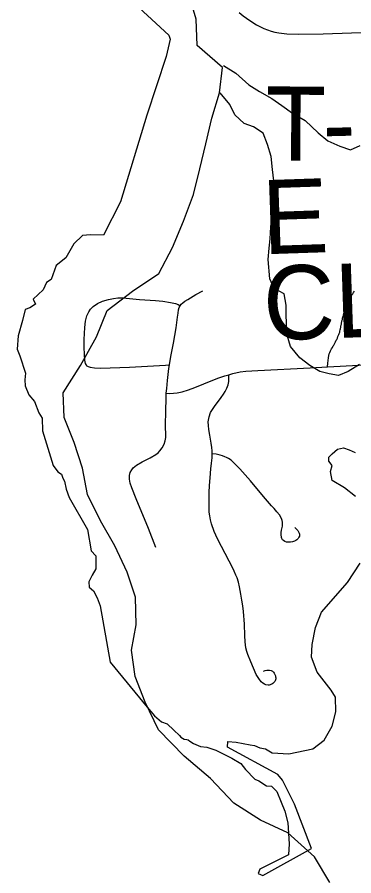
# Model space of a CAD drawing. Extents: x 63.4 to 97.4, y 0.4 to 22.4.
# Drawn here: x 67.709 to 67.967, y 19.757 to 20.415 of the extents above; entities that cross this region are included whole.
import ezdxf

# ---------------------------------------------------------------- set-up
doc = ezdxf.new("R2010")
doc.units = 0
for name, color, linetype in [('GM_X_County_Road', 7, 'Continuous'), ('GM_X_Major_Lake', 7, 'Continuous'), ('GM_X_Minor_River', 7, 'Continuous'), ('GM_X_Township_Road', 7, 'Continuous'), ('GM_X_Township_Road_Text', 7, 'Continuous'), ('SH_Cut_Line', 7, 'Continuous')]:
    doc.layers.add(name, color=color, linetype=linetype)

msp = doc.modelspace()

# ---------------------------------------------------------------- linework, layer by layer
at = {"layer": 'GM_X_County_Road'}
for points in [[(67.77988, 20.44361), (67.82559, 20.40119), (67.82657, 20.39823), (67.82361, 20.38475), (67.80865, 20.33987), (67.7886, 20.27328), (67.77544, 20.2478), (67.76557, 20.24813), (67.7595, 20.24747), (67.75275, 20.24106), (67.7465, 20.23038), (67.73927, 20.22445), (67.7354, 20.2138), (67.73188, 20.21164), (67.72924, 20.20588), (67.72152, 20.19881), (67.72333, 20.19503), (67.71905, 20.19207), (67.71544, 20.19075), (67.7133, 20.18237), (67.71001, 20.17053), (67.70935, 20.16034), (67.71132, 20.15541), (67.71576, 20.14209), (67.71527, 20.13699), (67.71544, 20.13222), (67.71823, 20.12548), (67.72267, 20.12039), (67.72596, 20.11168), (67.72842, 20.1074), (67.72875, 20.0977), (67.7368, 20.07123), (67.74042, 20.0663), (67.74338, 20.06449), (67.7442, 20.06137), (67.74552, 20.05923), (67.74683, 20.05298), (67.74905, 20.04672), (67.76329, 20.02222), (67.76607, 20.0058), (67.76969, 20.00185), (67.76969, 19.99183), (67.76689, 19.98705), (67.76426, 19.98196), (67.76447, 19.97796), (67.76771, 19.97505), (67.77051, 19.96979), (67.77297, 19.96355), (67.78054, 19.92042), (67.80896, 19.88581), (67.81449, 19.87929), (67.81991, 19.87468), (67.82435, 19.87304), (67.82945, 19.86827), (67.83372, 19.86417), (67.83471, 19.86285), (67.83734, 19.86121), (67.83931, 19.86104), (67.84046, 19.86088), (67.84161, 19.85989), (67.84441, 19.85791), (67.84967, 19.85562), (67.8546, 19.85529), (67.86151, 19.85282), (67.87367, 19.84674), (67.88058, 19.84263), (67.88419, 19.83819), (67.89139, 19.83054), (67.89455, 19.82947), (67.90047, 19.82553), (67.90425, 19.8252), (67.90573, 19.82372), (67.90836, 19.82109), (67.91165, 19.81303), (67.91428, 19.80613), (67.91667, 19.79719), (67.91773, 19.78096), (67.9172, 19.77271), (67.89512, 19.76154), (67.89406, 19.75835), (67.89752, 19.75675), (67.93476, 19.7775), (67.92186, 19.81142), (67.91268, 19.82977), (67.90895, 19.8343), (67.87052, 19.85531), (67.87078, 19.85943), (67.87704, 19.85903), (67.88781, 19.8569), (67.89113, 19.8565), (67.89526, 19.85464), (67.89952, 19.85397), (67.90457, 19.85092), (67.91758, 19.85009), (67.93582, 19.85384), (67.94447, 19.86049), (67.95072, 19.87127), (67.95338, 19.88217), (67.95325, 19.89348), (67.94992, 19.8988), (67.93915, 19.91263), (67.93476, 19.9242), (67.93543, 19.93391), (67.93795, 19.94708), (67.94261, 19.95865), (67.96242, 19.98153), (67.97214, 19.99642)], [(67.96841, 20.0475), (67.96016, 20.05402), (67.95059, 20.05974), (67.94939, 20.06665), (67.95072, 20.07131), (67.94806, 20.0745), (67.94806, 20.07769), (67.95059, 20.08009), (67.95471, 20.08368), (67.95923, 20.08474), (67.96375, 20.08328), (67.9684, 20.08119)]]:
    msp.add_lwpolyline(points, dxfattribs=at)
at = {"layer": 'GM_X_Major_Lake'}
msp.add_lwpolyline([(67.94886, 19.75138), (67.93709, 19.77115), (67.91659, 19.78939), (67.89572, 19.79927), (67.87522, 19.81219), (67.85738, 19.8312), (67.83726, 19.8483), (67.81752, 19.86845), (67.80727, 19.88973), (67.79967, 19.9095), (67.79701, 19.92965), (67.80042, 19.94904), (67.80003, 19.97033), (67.79357, 19.98933), (67.78408, 20.00948), (67.77307, 20.02886), (67.7632, 20.04901), (67.7594, 20.06915), (67.75294, 20.08892), (67.74534, 20.10793), (67.74458, 20.12693), (67.75785, 20.14784), (67.76999, 20.16989), (67.77834, 20.19003), (67.79769, 20.20486), (67.8178, 20.21855), (67.82842, 20.23831), (67.83676, 20.25846), (67.84435, 20.27898), (67.84928, 20.29875), (67.85383, 20.31775), (67.85838, 20.33751), (67.86444, 20.3569), (67.86672, 20.37628), (67.84736, 20.39338), (67.84659, 20.41353), (67.84052, 20.43329)], dxfattribs=at)
at = {"layer": 'GM_X_Minor_River'}
for points in [[(67.86743, 20.37798), (67.87695, 20.37194), (67.88687, 20.36323), (67.89487, 20.35795), (67.90439, 20.35267), (67.91201, 20.34738), (67.92039, 20.34133), (67.92991, 20.33567), (67.93984, 20.32621), (67.94746, 20.32016), (67.95659, 20.31602), (67.96458, 20.31339), (67.97216, 20.31647)], [(67.97152, 20.14874), (67.96281, 20.14338), (67.95562, 20.1403), (67.9484, 20.14141), (67.94117, 20.14328), (67.93356, 20.14781), (67.92593, 20.15386), (67.91867, 20.16257), (67.91558, 20.17283), (67.91547, 20.19412), (67.9139, 20.20287), (67.90629, 20.20701), (67.90283, 20.21423), (67.90162, 20.22905), (67.90233, 20.2378), (67.90305, 20.24503), (67.90376, 20.25416), (67.90448, 20.26177), (67.90482, 20.27014), (67.90516, 20.27813), (67.90586, 20.28954), (67.90505, 20.29829), (67.90386, 20.30817), (67.90116, 20.31728), (67.89769, 20.32601), (67.89045, 20.33093), (67.88322, 20.33355), (67.87598, 20.33998), (67.87214, 20.34795), (67.86488, 20.35705)]]:
    msp.add_lwpolyline(points, dxfattribs=at)
at = {"layer": 'GM_X_Township_Road'}
for points in [[(67.87941, 20.41862), (67.88255, 20.41605), (67.88748, 20.41235), (67.89268, 20.40912), (67.89819, 20.4064), (67.90391, 20.40423), (67.90684, 20.40344), (67.90983, 20.40289), (67.91595, 20.40228), (67.92522, 20.40203), (67.94386, 20.4023), (68.00163, 20.4043)], [(67.83424, 20.19374), (67.83508, 20.19494), (67.83615, 20.19597), (67.83779, 20.1971), (67.84, 20.19848), (67.84621, 20.20227), (67.85151, 20.20521)], [(67.94711, 20.14681), (67.94728, 20.14962), (67.94747, 20.15182), (67.94776, 20.15378), (67.94806, 20.1556), (67.94843, 20.15678), (67.94886, 20.15795), (67.94938, 20.15906), (67.94966, 20.15961), (67.94996, 20.16016), (67.95027, 20.16071), (67.95087, 20.16179), (67.95151, 20.16286), (67.95184, 20.16339), (67.95218, 20.16392), (67.95247, 20.16447), (67.95301, 20.16558), (67.9533, 20.16613), (67.95383, 20.16724), (67.95416, 20.16778), (67.95462, 20.16892), (67.95504, 20.17009), (67.95555, 20.17122), (67.95585, 20.17178), (67.95614, 20.17233), (67.95642, 20.17353), (67.95657, 20.17414), (67.95685, 20.17535), (67.95699, 20.17596), (67.95727, 20.17716), (67.9574, 20.17777), (67.95763, 20.17899), (67.95773, 20.17961), (67.95783, 20.18022), (67.95793, 20.18084), (67.95803, 20.18146), (67.95818, 20.18206), (67.95847, 20.18327), (67.95862, 20.18388), (67.95891, 20.18509), (67.95922, 20.18629), (67.9594, 20.18688), (67.95959, 20.18748), (67.95998, 20.18866), (67.96018, 20.18925), (67.96059, 20.19042), (67.961, 20.1916), (67.9612, 20.19219), (67.96142, 20.19277), (67.96164, 20.19336), (67.96187, 20.19394), (67.96235, 20.19508), (67.96261, 20.19565), (67.96312, 20.19679), (67.96338, 20.19735), (67.96364, 20.19792), (67.96392, 20.19848), (67.96448, 20.19958), (67.96508, 20.20067), (67.9654, 20.20121), (67.96573, 20.20174), (67.96607, 20.20227), (67.96641, 20.20279), (67.96711, 20.20381), (67.96784, 20.20481)], [(67.76284, 20.14746), (67.76179, 20.14943), (67.76126, 20.15205), (67.76087, 20.15624), (67.76061, 20.16188), (67.76074, 20.16791), (67.76113, 20.17709), (67.76179, 20.18194), (67.76281, 20.18593), (67.76427, 20.18915), (67.76558, 20.19112), (67.76755, 20.19309), (67.77098, 20.19531), (67.77476, 20.19715), (67.77922, 20.1986), (67.78302, 20.19936), (67.78643, 20.19978), (67.79023, 20.19978), (67.80295, 20.1986), (67.81524, 20.1976), (67.82088, 20.1972), (67.8268, 20.19631), (67.83059, 20.19543), (67.8326, 20.19462), (67.83424, 20.19374)], [(67.82599, 20.14829), (67.82708, 20.15468), (67.82904, 20.16504), (67.83114, 20.17684), (67.83219, 20.18502), (67.83271, 20.18811), (67.83305, 20.19055), (67.83354, 20.19232), (67.83424, 20.19374)], [(67.94711, 20.14681), (67.97106, 20.14802), (68.0557, 20.15015)], [(67.76284, 20.14746), (67.7652, 20.14654), (67.76847, 20.14602), (67.77306, 20.14589), (67.79548, 20.14668), (67.8231, 20.14814), (67.82599, 20.14829)], [(67.82356, 20.1267), (67.8239, 20.13026), (67.82441, 20.13632), (67.82552, 20.14554), (67.82599, 20.14829)], [(67.87144, 20.14076), (67.87467, 20.14171), (67.88021, 20.14294), (67.88443, 20.14349), (67.8937, 20.14408)], [(67.8937, 20.14408), (67.93391, 20.14615), (67.94711, 20.14681)], [(67.82356, 20.1267), (67.82628, 20.12641), (67.82899, 20.12655), (67.83199, 20.12684), (67.83585, 20.1277), (67.84057, 20.12913), (67.8454, 20.13094), (67.85933, 20.13673), (67.86392, 20.13843), (67.86838, 20.13987), (67.87144, 20.14076)], [(67.85877, 20.08017), (67.85868, 20.08232), (67.8584, 20.08505), (67.85792, 20.08842), (67.85687, 20.09457), (67.8562, 20.09868), (67.85586, 20.10179), (67.85575, 20.10458), (67.85631, 20.10847), (67.85753, 20.1118), (67.86042, 20.11641), (67.86565, 20.12337), (67.86743, 20.12581), (67.86876, 20.12782), (67.87009, 20.13038), (67.87087, 20.13304), (67.87143, 20.1356), (67.87158, 20.13794), (67.87144, 20.14076)], [(67.81564, 20.00843), (67.81005, 20.02278), (67.80061, 20.04573), (67.79707, 20.05399), (67.79602, 20.05766), (67.79536, 20.06081), (67.79532, 20.0622), (67.79536, 20.06356), (67.79602, 20.06579), (67.79707, 20.06775), (67.79828, 20.06936), (67.79942, 20.07055), (67.80065, 20.0715), (67.80506, 20.07405), (67.81135, 20.0772), (67.81546, 20.07968), (67.81726, 20.08103), (67.81868, 20.08249), (67.82048, 20.08483), (67.8219, 20.08747), (67.82282, 20.09002), (67.8232, 20.0927), (67.82315, 20.09621), (67.82302, 20.09962), (67.82302, 20.10316), (67.82315, 20.11181), (67.8234, 20.12391), (67.82356, 20.1267)], [(67.89797, 19.91349), (67.89929, 19.9139), (67.90048, 19.91421), (67.90166, 19.91421), (67.90264, 19.91416), (67.90391, 19.91398), (67.90489, 19.91344), (67.90573, 19.9126), (67.9063, 19.91184), (67.90684, 19.91081), (67.90718, 19.90983), (67.90737, 19.90906), (67.90747, 19.90844), (67.90747, 19.90756), (67.9073, 19.90681), (67.90706, 19.90615), (67.90671, 19.90559), (67.90633, 19.90507), (67.90571, 19.90443), (67.90515, 19.90393), (67.90449, 19.90348), (67.90378, 19.90317), (67.90304, 19.90298), (67.90231, 19.90283), (67.90161, 19.90275), (67.8999, 19.90298), (67.89875, 19.90344), (67.89745, 19.90423), (67.89629, 19.90521), (67.89449, 19.90774), (67.89247, 19.91099), (67.88824, 19.92066), (67.88612, 19.92622), (67.88531, 19.92866), (67.88457, 19.93146), (67.88402, 19.93593), (67.88369, 19.9408), (67.88357, 19.94947), (67.88268, 19.95925), (67.88223, 19.96359), (67.88157, 19.96781), (67.88079, 19.9726), (67.87967, 19.97815), (67.87878, 19.98171), (67.87778, 19.98494), (67.87691, 19.98704), (67.87556, 19.99016), (67.87345, 19.99439), (67.87167, 19.99784), (67.86285, 20.01495), (67.86018, 20.02058), (67.85812, 20.02649), (67.85736, 20.02951), (67.85682, 20.03252), (67.85654, 20.03541), (67.85631, 20.04153), (67.85654, 20.05042), (67.85676, 20.05576), (67.85709, 20.06166), (67.85776, 20.06855), (67.8582, 20.073), (67.85865, 20.077), (67.85877, 20.08017)], [(67.92199, 20.02353), (67.92331, 20.02249), (67.92439, 20.02131), (67.92498, 20.0204), (67.92544, 20.01942), (67.92565, 20.01852), (67.92568, 20.01771), (67.92555, 20.01708), (67.92524, 20.01635), (67.9246, 20.01532), (67.92356, 20.01423), (67.92276, 20.01364), (67.92189, 20.01316), (67.92032, 20.01257), (67.91872, 20.01236), (67.91722, 20.01236), (67.91562, 20.0125), (67.91433, 20.01299), (67.91336, 20.01358), (67.91266, 20.0143), (67.91214, 20.0151), (67.91179, 20.01597), (67.91148, 20.01824), (67.91158, 20.01984), (67.91196, 20.02162), (67.91259, 20.02472), (67.91273, 20.02611), (67.91271, 20.02766), (67.91238, 20.02914), (67.91188, 20.0306), (67.91035, 20.03324), (67.90839, 20.03562), (67.9062, 20.0381), (67.90424, 20.04039), (67.89818, 20.04742), (67.88815, 20.05941), (67.88003, 20.06863), (67.87566, 20.07299), (67.87316, 20.07517), (67.8712, 20.07648), (67.86967, 20.07735), (67.86843, 20.07789), (67.86674, 20.07867), (67.86476, 20.07922), (67.86187, 20.07978), (67.85877, 20.08017)]]:
    msp.add_lwpolyline(points, dxfattribs=at)
at = {"layer": 'SH_Cut_Line'}
for points in [[(67.77988, 20.44361), (67.82559, 20.40119), (67.82657, 20.39823), (67.82361, 20.38475), (67.80865, 20.33987), (67.7886, 20.27328), (67.77544, 20.2478), (67.76557, 20.24813), (67.7595, 20.24747), (67.75275, 20.24106), (67.7465, 20.23038), (67.73927, 20.22445), (67.7354, 20.2138), (67.73188, 20.21164), (67.72924, 20.20588), (67.72152, 20.19881), (67.72333, 20.19503), (67.71905, 20.19207), (67.71544, 20.19075), (67.7133, 20.18237), (67.71001, 20.17053), (67.70935, 20.16034), (67.71132, 20.15541), (67.71576, 20.14209), (67.71527, 20.13699), (67.71544, 20.13222), (67.71823, 20.12548), (67.72267, 20.12039), (67.72596, 20.11168), (67.72842, 20.1074), (67.72875, 20.0977), (67.7368, 20.07123), (67.74042, 20.0663), (67.74338, 20.06449), (67.7442, 20.06137), (67.74552, 20.05923), (67.74683, 20.05298), (67.74905, 20.04672), (67.76329, 20.02222), (67.76607, 20.0058), (67.76969, 20.00185), (67.76969, 19.99183), (67.76689, 19.98705), (67.76426, 19.98196), (67.76447, 19.97796), (67.76771, 19.97505), (67.77051, 19.96979), (67.77297, 19.96355), (67.78054, 19.92042), (67.80896, 19.88581), (67.81449, 19.87929), (67.81991, 19.87468), (67.82435, 19.87304), (67.82945, 19.86827), (67.83372, 19.86417), (67.83471, 19.86285), (67.83734, 19.86121), (67.83931, 19.86104), (67.84046, 19.86088), (67.84161, 19.85989), (67.84441, 19.85791), (67.84967, 19.85562), (67.8546, 19.85529), (67.86151, 19.85282), (67.87367, 19.84674), (67.88058, 19.84263), (67.88419, 19.83819), (67.89139, 19.83054), (67.89455, 19.82947), (67.90047, 19.82553), (67.90425, 19.8252), (67.90573, 19.82372), (67.90836, 19.82109), (67.91165, 19.81303), (67.91428, 19.80613), (67.91667, 19.79719), (67.91773, 19.78096), (67.9172, 19.77271), (67.89512, 19.76154), (67.89406, 19.75835), (67.89752, 19.75675), (67.93476, 19.7775), (67.92186, 19.81142), (67.91268, 19.82977), (67.90895, 19.8343), (67.87052, 19.85531), (67.87078, 19.85943), (67.87704, 19.85903), (67.88781, 19.8569), (67.89113, 19.8565), (67.89526, 19.85464), (67.89952, 19.85397), (67.90457, 19.85092), (67.91758, 19.85009), (67.93582, 19.85384), (67.94447, 19.86049), (67.95072, 19.87127), (67.95338, 19.88217), (67.95325, 19.89348), (67.94992, 19.8988), (67.93915, 19.91263), (67.93476, 19.9242), (67.93543, 19.93391), (67.93795, 19.94708), (67.94261, 19.95865), (67.96242, 19.98153), (67.97214, 19.99642)], [(67.96841, 20.0475), (67.96016, 20.05402), (67.95059, 20.05974), (67.94939, 20.06665), (67.95072, 20.07131), (67.94806, 20.0745), (67.94806, 20.07769), (67.95059, 20.08009), (67.95471, 20.08368), (67.95923, 20.08474), (67.96375, 20.08328), (67.9684, 20.08119)]]:
    msp.add_lwpolyline(points, dxfattribs=at)

# ---------------------------------------------------------------- texts
at = {"layer": 'GM_X_Township_Road_Text'}
for s, height, rotation, p in [('T', 0.05682, 359.61432, (67.89944, 20.30514)), ('-', 0.05682, 1.38878, (67.94387, 20.30487)), ('E BEACH', 0.056818, 1.94165, (67.89795, 20.23312)), ('CLUB RD', 0.056818, 1.90252, (67.89868, 20.1671))]:
    msp.add_text(s, height=height, rotation=rotation, dxfattribs=at).set_placement(p)

doc.saveas('drawing.dxf')
